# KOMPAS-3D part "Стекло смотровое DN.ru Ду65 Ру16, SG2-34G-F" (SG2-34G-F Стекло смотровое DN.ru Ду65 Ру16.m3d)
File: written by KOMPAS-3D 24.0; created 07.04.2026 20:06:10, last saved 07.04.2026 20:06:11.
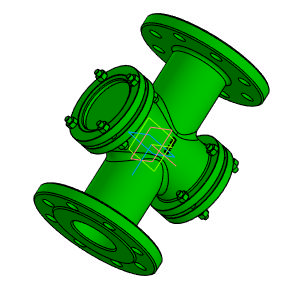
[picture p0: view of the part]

Document properties: Автор: Main; Полное имя файла: D:\DN.ru Аутсерс\Стекло смотровое DN.ru\SG2-34G-F Стекло смотровое DN.ru Ду65 Ру16\SG2-34G-F Стекло смотровое DN.ru Ду65 Ру16.m3d

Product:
- Body: Тело 1  | qty 1
    Масса: 13.01185
- Part/product: Стекло смотровое DN.ru Ду65 Ру16  | designation SG2-34G-F
    Масса: 14
    Раздел спецификации: Прочие изделия
    Примечание: D500-00085

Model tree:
1. Операция без истории:1

Expressions: SG2-34G-F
